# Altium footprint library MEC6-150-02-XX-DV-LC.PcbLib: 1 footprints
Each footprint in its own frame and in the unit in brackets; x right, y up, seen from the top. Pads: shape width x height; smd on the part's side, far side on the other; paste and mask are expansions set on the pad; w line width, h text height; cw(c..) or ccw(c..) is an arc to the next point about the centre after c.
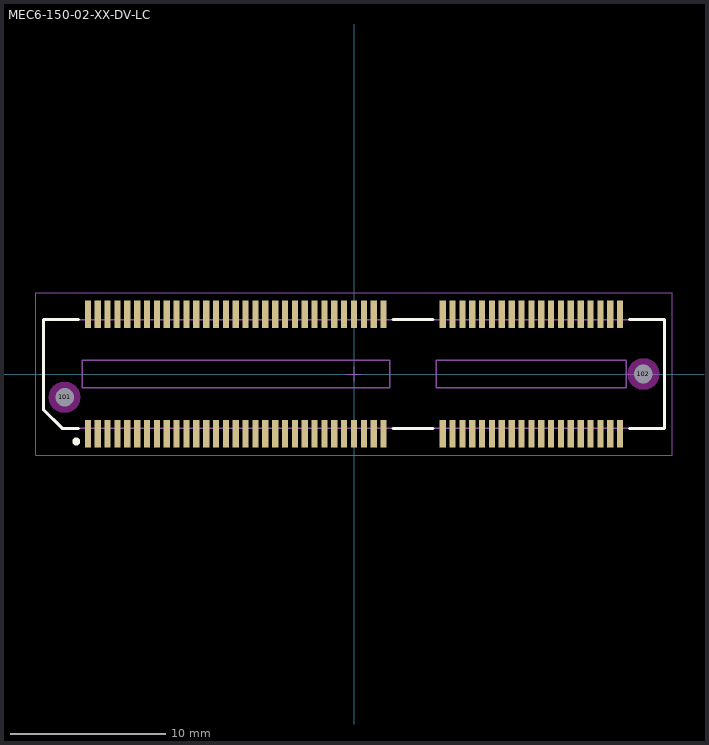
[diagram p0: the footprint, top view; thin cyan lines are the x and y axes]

## MEC6-150-02-XX-DV-LC [mm] "0.635mm pitch, 100 pin, micro edge card; vertical, w/locking clips, SMT"
height 8.65
pads (102):
  rect 0.4x1.8 smd mask+0: 1(-17.145,-3.848) 2(-17.145,3.848) 3(-16.51,-3.848) 4(-16.51,3.848) 5(-15.875,-3.848) 6(-15.875,3.848) 7(-15.24,-3.848) 8(-15.24,3.848) 9(-14.605,-3.848) 10(-14.605,3.848) 11(-13.97,-3.848) 12(-13.97,3.848) 13(-13.335,-3.848) 14(-13.335,3.848) 15(-12.7,-3.848) 16(-12.7,3.848) 17(-12.065,-3.848) 18(-12.065,3.848) 19(-11.43,-3.848) 20(-11.43,3.848) 21(-10.795,-3.848) 22(-10.795,3.848) 23(-10.16,-3.848) 24(-10.16,3.848) 25(-9.525,-3.848) 26(-9.525,3.848) 27(-8.89,-3.848) 28(-8.89,3.848) 29(-8.255,-3.848) 30(-8.255,3.848) 31(-7.62,-3.848) 32(-7.62,3.848) 33(-6.985,-3.848) 34(-6.985,3.848) 35(-6.35,-3.848) 36(-6.35,3.848) 37(-5.715,-3.848) 38(-5.715,3.848) 39(-5.08,-3.848) 40(-5.08,3.848) 41(-4.445,-3.848) 42(-4.445,3.848) 43(-3.81,-3.848) 44(-3.81,3.848) 45(-3.175,-3.848) 46(-3.175,3.848) 47(-2.54,-3.848) 48(-2.54,3.848) 49(-1.905,-3.848) 50(-1.905,3.848) 51(-1.27,-3.848) 52(-1.27,3.848) 53(-0.635,-3.848) 54(-0.635,3.848) 55(0,-3.848) 56(0,3.848) 57(0.635,-3.848) 58(0.635,3.848) 59(1.27,-3.848) 60(1.27,3.848) 61(1.905,-3.848) 62(1.905,3.848) 63(5.715,-3.848) 64(5.715,3.848) 65(6.35,-3.848) 66(6.35,3.848) 67(6.985,-3.848) 68(6.985,3.848) 69(7.62,-3.848) 70(7.62,3.848) 71(8.255,-3.848) 72(8.255,3.848) 73(8.89,-3.848) 74(8.89,3.848) 75(9.525,-3.848) 76(9.525,3.848) 77(10.16,-3.848) 78(10.16,3.848) 79(10.795,-3.848) 80(10.795,3.848) 81(11.43,-3.848) 82(11.43,3.848) 83(12.065,-3.848) 84(12.065,3.848) 85(12.7,-3.848) 86(12.7,3.848) 87(13.335,-3.848) 88(13.335,3.848) 89(13.97,-3.848) 90(13.97,3.848) 91(14.605,-3.848) 92(14.605,3.848) 93(15.24,-3.848) 94(15.24,3.848) 95(15.875,-3.848) 96(15.875,3.848) 97(16.51,-3.848) 98(16.51,3.848) 99(17.145,-3.848) 100(17.145,3.848)
  round 1 hole 1.2 unplated mask+0: 101(-18.644,-1.499) 102(18.644,0)
Top Overlay:
  circle w0.25: c-17.9,-4.35 r0.125
  lines w0.2: -17.75,-3.5 -18.8,-3.5 -20,-2.3 -20,3.5 -17.75,3.5 ; 2.5,-3.5 5.1,-3.5 ; 2.5,3.5 5.1,3.5 ; 17.75,-3.5 20,-3.5 20,3.5 17.75,3.5
Keep-Out Layer:
  pour cut-out: -17.641,-1.5 -17.676,-1.239 -17.777,-0.996 -17.937,-0.787 -18.146,-0.627 -18.389,-0.526 -18.65,-0.491 -18.911,-0.526 -19.154,-0.627 -19.363,-0.787 -19.523,-0.996 -19.624,-1.239 -19.659,-1.5 -19.624,-1.761 -19.523,-2.004 -19.363,-2.213 -19.154,-2.373 -18.911,-2.474 -18.65,-2.509 -18.389,-2.474 -18.146,-2.373 -17.937,-2.213 -17.777,-2.004 -17.676,-1.761
  pour cut-out: 19.659,0 19.624,0.261 19.523,0.504 19.363,0.713 19.154,0.873 18.911,0.974 18.65,1.009 18.389,0.974 18.146,0.873 17.937,0.713 17.777,0.504 17.676,0.261 17.641,0 17.676,-0.261 17.777,-0.504 17.937,-0.713 18.146,-0.873 18.389,-0.974 18.65,-1.009 18.911,-0.974 19.154,-0.873 19.363,-0.713 19.523,-0.504 19.624,-0.261
Mechanical 13:
  lines w0.1: -20,-2.3 -18.8,-3.5 20,-3.5 20,3.5 -20,3.5 -20,-2.3 ; -17.5,-0.9 2.3,-0.9 2.3,0.9 -17.5,0.9 -17.5,-0.9 ; 5.3,-0.9 17.55,-0.9 17.55,0.9 5.3,0.9 5.3,-0.9
  text ".Designator" at 0,0 h1.52
Mechanical 15:
  lines w0.05: -0.5,0 0.5,0 ; 0,-0.5 0,0.5 ; -20.5,-5.25 20.5,-5.25 20.5,5.25 -20.5,5.25 -20.5,-5.25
